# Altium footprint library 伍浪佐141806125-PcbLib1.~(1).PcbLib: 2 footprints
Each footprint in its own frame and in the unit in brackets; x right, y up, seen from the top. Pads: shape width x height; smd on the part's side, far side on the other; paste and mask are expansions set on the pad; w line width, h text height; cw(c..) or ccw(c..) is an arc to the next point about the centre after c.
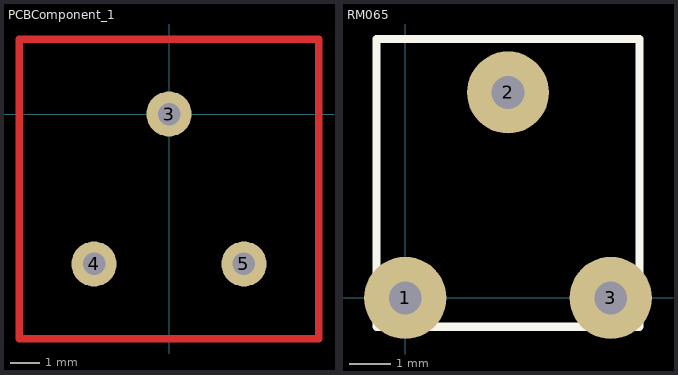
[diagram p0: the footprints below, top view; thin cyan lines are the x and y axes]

## PCBComponent_1 [mil]
pads (3):
  round 60 hole 30: 3(0,0) 4(-100,-200) 5(100,-200)
Top Layer:
  lines w10: -200,-300 -200,-200 -200,100 200,100 200,-300 -200,-300

## RM065 [mm]
pads (3):
  round 2 hole 0.8: 1(0,0) 2(2.5,5) 3(5,0)
Top Overlay:
  lines w0.2: -0.7,-0.7 -0.7,6.3 5.7,6.3 5.7,-0.7 -0.7,-0.7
